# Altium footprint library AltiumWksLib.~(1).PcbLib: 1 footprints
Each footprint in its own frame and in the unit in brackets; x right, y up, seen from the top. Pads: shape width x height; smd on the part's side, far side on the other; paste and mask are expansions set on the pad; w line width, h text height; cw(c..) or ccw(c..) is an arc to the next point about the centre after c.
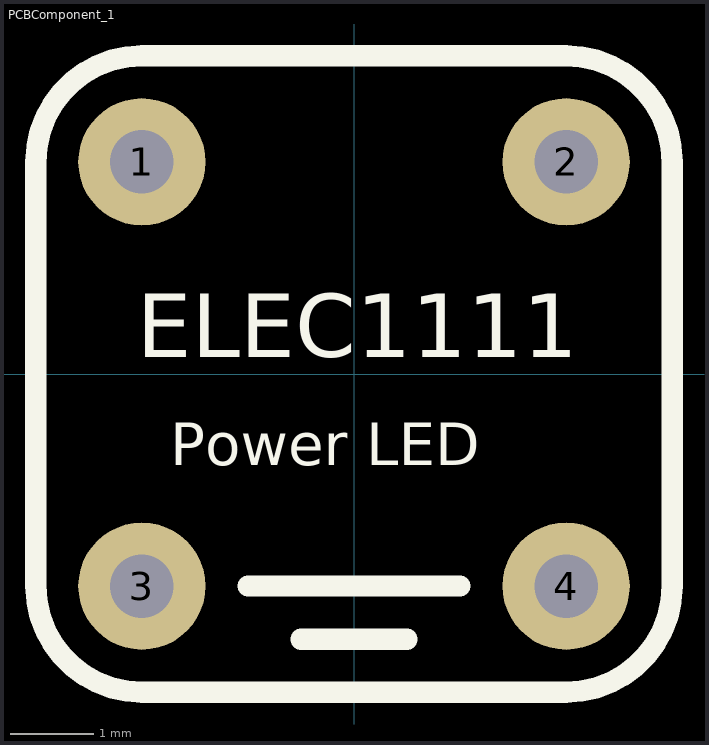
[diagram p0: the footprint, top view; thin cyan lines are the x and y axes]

## PCBComponent_1 [mil]
pads (4):
  round 60 hole 30: 1(-100,100) 2(100,100) 3(-100,-100) 4(100,-100)
Top Overlay:
  lines w10: -50,-100 50,-100 ; -25,-125 25,-125 ; -150,-100 ccw(c-100,-100) -100,-150 100,-150 ccw(c100,-100) 150,-100 150,100 ccw(c100,100) 100,150 -100,150 ccw(c-100,100) -150,100 -150,-100
  text "ELEC1111" at -102.47,8 h30
  text "Power LED" at -86.64,-43 h20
